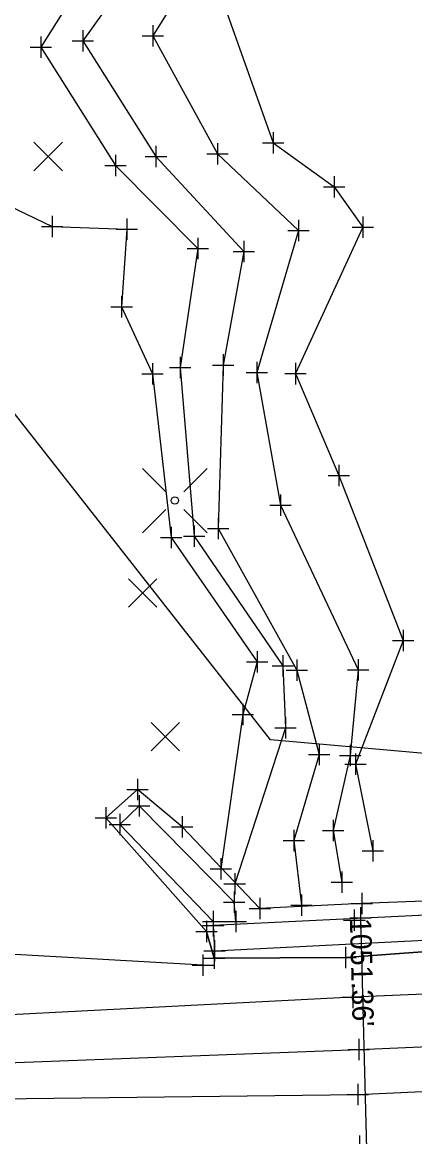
# Model space of a CAD drawing. Extents: x 211013 to 211654, y 505587 to 505872.
# Drawn here: x 211293.9 to 211312.2, y 505734.3 to 505786.5 of the extents above; entities that cross this region are included whole.
import ezdxf

# ---------------------------------------------------------------- set-up
doc = ezdxf.new("R2010")
doc.units = 0
for name, color, linetype in [('_CIVIL_CONSTRUCTION', 7, 'Continuous'), ('AP_P_PCI_Pavement', 7, 'Continuous'), ('BR_X_Rail_Centerline', 7, 'Continuous'), ('DR_X_Storm_Sewer', 7, 'Continuous'), ('DV_X_Section_VMS_Line', 7, 'Continuous'), ('GE_X_Alignment_1000_Curve_Data', 7, 'Continuous'), ('GE_X_Alignment_100_Curve_Data', 7, 'Continuous'), ('GE_X_Alignment_100_Stations', 7, 'Continuous'), ('GE_X_Alignment_500_Stations', 7, 'Continuous'), ('RW_P_Esmt_SH', 7, 'Continuous'), ('RW_X_Esmt_SH', 7, 'Continuous'), ('SC_Scratch1', 7, 'Continuous'), ('SC_Scratch10', 7, 'Continuous'), ('SC_Scratch3', 7, 'Continuous'), ('SV_X_Control_Cells_Found', 7, 'Continuous'), ('SV_X_Terrain_Break_Line', 7, 'Continuous')]:
    doc.layers.add(name, color=color, linetype=linetype)

msp = doc.modelspace()

# ---------------------------------------------------------------- linework, layer by layer
at = {"layer": '_CIVIL_CONSTRUCTION'}
msp.add_lwpolyline([(211321.115, 505749.559), (211319.635, 505750.939), (211314.771, 505745.411), (211309.764, 505745.231), (211304.987, 505744.992), (211301.351, 505748.814), (211299.272, 505750.564), (211297.783, 505749.234), (211302.497, 505743.915), (211302.86, 505742.67), (211309.002, 505742.706), (211316.82, 505743.273), (211317, 505744.987), (211318.809, 505747.038)], close=True, dxfattribs=at)
at = {"layer": 'AP_P_PCI_Pavement'}
msp.add_lwpolyline([(211327.503, 505810.82), (211323.319, 505809.929), (211317.381, 505803.934), (211308.061, 505794.296), (211303.39, 505787.114), (211305.619, 505780.843), (211308.475, 505778.776), (211309.82, 505776.891), (211306.66, 505770.032), (211308.698, 505765.258), (211311.708, 505757.543), (211309.473, 505751.753), (211310.28, 505747.694)], dxfattribs=at)
at = {"layer": 'BR_X_Rail_Centerline'}
for p, q in [((211305.491, 505752.893), (211283.423, 505780.994)), ((211344.613, 505749.38), (211305.491, 505752.893))]:
    msp.add_line(p, q, dxfattribs=at)
at = {"layer": 'DR_X_Storm_Sewer'}
msp.add_line((211309.709, 505744.552), (211310.772, 505703.905), dxfattribs=at)
at = {"layer": 'DV_X_Section_VMS_Line'}
for p, q in [((211296.713, 505786.108), (211296.713, 505785.108)), ((211299.982, 505786.35), (211299.982, 505785.35)), ((211294.742, 505785.823), (211294.742, 505784.823)), ((211296.213, 505785.608), (211297.213, 505785.608)), ((211296.713, 505785.608), (211296.713, 505785.608)), ((211299.482, 505785.85), (211300.482, 505785.85)), ((211299.982, 505785.85), (211299.982, 505785.85)), ((211294.242, 505785.323), (211295.242, 505785.323)), ((211294.742, 505785.323), (211294.742, 505785.323)), ((211305.619, 505781.343), (211305.619, 505780.343)), ((211303.013, 505780.82), (211303.013, 505779.82)), ((211305.119, 505780.843), (211306.119, 505780.843)), ((211305.619, 505780.843), (211305.619, 505780.843)), ((211298.229, 505780.271), (211298.229, 505779.271)), ((211300.132, 505780.705), (211300.132, 505779.705)), ((211302.513, 505780.32), (211303.513, 505780.32)), ((211303.013, 505780.32), (211303.013, 505780.32)), ((211297.729, 505779.771), (211298.729, 505779.771)), ((211298.229, 505779.771), (211298.229, 505779.771)), ((211299.632, 505780.205), (211300.632, 505780.205)), ((211300.132, 505780.205), (211300.132, 505780.205)), ((211308.475, 505779.276), (211308.475, 505778.276)), ((211307.975, 505778.776), (211308.975, 505778.776)), ((211308.475, 505778.776), (211308.475, 505778.776)), ((211295.266, 505777.416), (211295.266, 505776.416)), ((211298.771, 505777.292), (211298.771, 505776.292)), ((211306.808, 505777.237), (211306.808, 505776.237)), ((211309.82, 505777.391), (211309.82, 505776.391)), ((211294.766, 505776.916), (211295.766, 505776.916)), ((211295.266, 505776.916), (211295.266, 505776.916)), ((211298.271, 505776.792), (211299.271, 505776.792)), ((211298.771, 505776.792), (211298.771, 505776.792)), ((211306.308, 505776.737), (211307.308, 505776.737)), ((211306.808, 505776.737), (211306.808, 505776.737)), ((211309.32, 505776.891), (211310.32, 505776.891)), ((211309.82, 505776.891), (211309.82, 505776.891)), ((211302.084, 505776.392), (211302.084, 505775.392)), ((211304.247, 505776.25), (211304.247, 505775.25)), ((211301.584, 505775.892), (211302.584, 505775.892)), ((211302.084, 505775.892), (211302.084, 505775.892)), ((211303.747, 505775.75), (211304.747, 505775.75)), ((211304.247, 505775.75), (211304.247, 505775.75)), ((211298.524, 505773.661), (211298.524, 505772.661)), ((211298.024, 505773.161), (211299.024, 505773.161)), ((211298.524, 505773.161), (211298.524, 505773.161)), ((211303.284, 505770.937), (211303.284, 505769.937)), ((211299.968, 505770.522), (211299.968, 505769.522)), ((211301.268, 505770.827), (211301.268, 505769.827)), ((211302.784, 505770.437), (211303.784, 505770.437)), ((211303.284, 505770.437), (211303.284, 505770.437)), ((211304.847, 505770.58), (211304.847, 505769.58)), ((211306.66, 505770.532), (211306.66, 505769.532)), ((211299.468, 505770.022), (211300.468, 505770.022)), ((211299.968, 505770.022), (211299.968, 505770.022)), ((211300.768, 505770.327), (211301.768, 505770.327)), ((211301.268, 505770.327), (211301.268, 505770.327)), ((211304.347, 505770.08), (211305.347, 505770.08)), ((211304.847, 505770.08), (211304.847, 505770.08)), ((211306.16, 505770.032), (211307.16, 505770.032)), ((211306.66, 505770.032), (211306.66, 505770.032)), ((211308.698, 505765.758), (211308.698, 505764.758)), ((211308.198, 505765.258), (211309.198, 505765.258)), ((211308.698, 505765.258), (211308.698, 505765.258)), ((211305.963, 505764.381), (211305.963, 505763.381)), ((211305.463, 505763.881), (211306.463, 505763.881)), ((211305.963, 505763.881), (211305.963, 505763.881)), ((211303.046, 505763.284), (211303.046, 505762.284)), ((211300.847, 505762.861), (211300.847, 505761.861)), ((211301.924, 505762.93), (211301.924, 505761.93)), ((211302.546, 505762.784), (211303.546, 505762.784)), ((211303.046, 505762.784), (211303.046, 505762.784)), ((211300.347, 505762.361), (211301.347, 505762.361)), ((211300.847, 505762.361), (211300.847, 505762.361)), ((211301.424, 505762.43), (211302.424, 505762.43)), ((211301.924, 505762.43), (211301.924, 505762.43)), ((211311.708, 505758.043), (211311.708, 505757.043)), ((211311.208, 505757.543), (211312.208, 505757.543)), ((211311.708, 505757.543), (211311.708, 505757.543)), ((211304.863, 505757.046), (211304.863, 505756.046)), ((211306.066, 505756.847), (211306.066, 505755.847)), ((211304.363, 505756.546), (211305.363, 505756.546)), ((211304.863, 505756.546), (211304.863, 505756.546)), ((211305.566, 505756.347), (211306.566, 505756.347)), ((211306.066, 505756.347), (211306.066, 505756.347)), ((211306.73, 505756.65), (211306.73, 505755.65)), ((211309.606, 505756.673), (211309.606, 505755.673)), ((211306.23, 505756.15), (211307.23, 505756.15)), ((211306.73, 505756.15), (211306.73, 505756.15)), ((211309.106, 505756.173), (211310.106, 505756.173)), ((211309.606, 505756.173), (211309.606, 505756.173)), ((211304.191, 505754.57), (211304.191, 505753.57)), ((211303.691, 505754.07), (211304.691, 505754.07)), ((211304.191, 505754.07), (211304.191, 505754.07)), ((211306.192, 505753.949), (211306.192, 505752.949)), ((211305.692, 505753.449), (211306.692, 505753.449)), ((211306.192, 505753.449), (211306.192, 505753.449)), ((211307.777, 505752.7), (211307.777, 505751.7)), ((211309.228, 505752.656), (211309.228, 505751.656)), ((211307.277, 505752.2), (211308.277, 505752.2)), ((211307.777, 505752.2), (211307.777, 505752.2)), ((211308.728, 505752.156), (211309.728, 505752.156)), ((211309.228, 505752.156), (211309.228, 505752.156)), ((211309.473, 505752.253), (211309.473, 505751.253)), ((211308.973, 505751.753), (211309.973, 505751.753)), ((211309.473, 505751.753), (211309.473, 505751.753)), ((211299.272, 505751.064), (211299.272, 505750.064)), ((211298.772, 505750.564), (211299.772, 505750.564)), ((211299.272, 505750.564), (211299.272, 505750.564)), ((211299.339, 505750.302), (211299.339, 505749.302)), ((211297.783, 505749.734), (211297.783, 505748.734)), ((211298.839, 505749.802), (211299.839, 505749.802)), ((211299.339, 505749.802), (211299.339, 505749.802)), ((211297.283, 505749.234), (211298.283, 505749.234)), ((211297.783, 505749.234), (211297.783, 505749.234)), ((211298.443, 505749.431), (211298.443, 505748.431)), ((211301.351, 505749.314), (211301.351, 505748.314)), ((211308.422, 505749.142), (211308.422, 505748.142)), ((211297.943, 505748.931), (211298.943, 505748.931)), ((211298.443, 505748.931), (211298.443, 505748.931)), ((211300.851, 505748.814), (211301.851, 505748.814)), ((211301.351, 505748.814), (211301.351, 505748.814)), ((211306.587, 505748.682), (211306.587, 505747.682)), ((211307.922, 505748.642), (211308.922, 505748.642)), ((211308.422, 505748.642), (211308.422, 505748.642)), ((211306.087, 505748.182), (211307.087, 505748.182)), ((211306.587, 505748.182), (211306.587, 505748.182)), ((211310.28, 505748.194), (211310.28, 505747.194)), ((211309.78, 505747.694), (211310.78, 505747.694)), ((211310.28, 505747.694), (211310.28, 505747.694)), ((211303.17, 505747.354), (211303.17, 505746.354)), ((211302.67, 505746.854), (211303.67, 505746.854)), ((211303.17, 505746.854), (211303.17, 505746.854)), ((211303.816, 505746.645), (211303.816, 505745.645)), ((211308.829, 505746.725), (211308.829, 505745.725)), ((211303.316, 505746.145), (211304.316, 505746.145)), ((211303.816, 505746.145), (211303.816, 505746.145)), ((211308.329, 505746.225), (211309.329, 505746.225)), ((211308.829, 505746.225), (211308.829, 505746.225)), ((211303.798, 505745.796), (211303.798, 505744.796)), ((211304.987, 505745.492), (211304.987, 505744.492)), ((211306.944, 505745.647), (211306.944, 505744.647)), ((211309.764, 505745.731), (211309.764, 505744.731)), ((211302.816, 505744.889), (211302.816, 505743.889)), ((211303.298, 505745.296), (211304.298, 505745.296)), ((211303.798, 505745.296), (211303.798, 505745.296)), ((211303.864, 505744.88), (211303.864, 505743.88)), ((211304.487, 505744.992), (211305.487, 505744.992)), ((211304.987, 505744.992), (211304.987, 505744.992)), ((211306.444, 505745.147), (211307.444, 505745.147)), ((211306.944, 505745.147), (211306.944, 505745.147)), ((211309.264, 505745.231), (211310.264, 505745.231)), ((211309.419, 505744.947), (211309.419, 505743.947)), ((211309.764, 505745.231), (211309.764, 505745.231)), ((211302.316, 505744.389), (211303.316, 505744.389)), ((211302.497, 505744.415), (211302.497, 505743.415)), ((211302.81, 505744.69), (211302.81, 505743.69)), ((211302.816, 505744.389), (211302.816, 505744.389)), ((211303.364, 505744.38), (211304.364, 505744.38)), ((211303.864, 505744.38), (211303.864, 505744.38)), ((211308.919, 505744.447), (211309.919, 505744.447)), ((211309.419, 505744.447), (211309.419, 505744.447)), ((211301.997, 505743.915), (211302.997, 505743.915)), ((211302.31, 505744.19), (211303.31, 505744.19)), ((211302.497, 505743.915), (211302.497, 505743.915)), ((211302.81, 505744.19), (211302.81, 505744.19)), ((211302.87, 505743.515), (211302.87, 505742.515)), ((211302.318, 505742.837), (211302.318, 505741.837)), ((211302.37, 505743.015), (211303.37, 505743.015)), ((211302.86, 505743.17), (211302.86, 505742.17)), ((211302.87, 505743.015), (211302.87, 505743.015)), ((211309.002, 505743.206), (211309.002, 505742.206)), ((211301.818, 505742.337), (211302.818, 505742.337)), ((211302.318, 505742.337), (211302.318, 505742.337)), ((211302.36, 505742.67), (211303.36, 505742.67)), ((211302.86, 505742.67), (211302.86, 505742.67)), ((211308.502, 505742.706), (211309.502, 505742.706)), ((211309.002, 505742.706), (211309.002, 505742.706)), ((211309.356, 505741.335), (211309.356, 505740.335)), ((211308.856, 505740.835), (211309.856, 505740.835)), ((211309.356, 505740.835), (211309.356, 505740.835)), ((211309.635, 505738.895), (211309.635, 505737.895)), ((211309.135, 505738.395), (211310.135, 505738.395)), ((211309.635, 505738.395), (211309.635, 505738.395)), ((211309.586, 505736.786), (211309.586, 505735.786)), ((211309.086, 505736.286), (211310.086, 505736.286)), ((211309.586, 505736.286), (211309.586, 505736.286)), ((211309.664, 505734.365), (211309.664, 505733.365)), ((211309.664, 505734.365), (211309.664, 505733.365))]:
    msp.add_line(p, q, dxfattribs=at)
at = {"layer": 'GE_X_Alignment_1000_Curve_Data'}
msp.add_lwpolyline([(211356.76, 505857.013), (211347.897, 505835.841), (211344.58, 505824.107), (211344.082, 505818.007), (211333.421, 505816.177), (211323.913, 505812.659), (211316.504, 505807.568), (211303.378, 505794.919), (211296.713, 505785.608), (211300.132, 505780.205), (211304.247, 505775.75), (211303.284, 505770.437), (211303.046, 505762.784), (211306.73, 505756.15), (211307.777, 505752.2), (211306.587, 505748.182), (211306.944, 505745.147)], dxfattribs=at)
at = {"layer": 'GE_X_Alignment_100_Curve_Data'}
msp.add_lwpolyline([(211264.741, 505737.499), (211284.908, 505737.456), (211309.635, 505738.395), (211334.721, 505739.468), (211359.035, 505740.326), (211410.048, 505742.397), (211459.85, 505743.658), (211510.023, 505745.433), (211559.895, 505747.411), (211609.683, 505748.573), (211648.059, 505750.315)], dxfattribs=at)
at = {"layer": 'GE_X_Alignment_100_Stations'}
for points in [[(211333.611, 505861.656), (211320.184, 505846.845), (211302.496, 505826.303), (211296.037, 505815.121), (211294.576, 505796.638), (211295.648, 505794.362), (211291.368, 505793.326), (211288.466, 505788.138), (211290.773, 505779.079), (211295.266, 505776.916), (211298.771, 505776.792), (211298.524, 505773.161), (211299.968, 505770.022), (211300.847, 505762.361), (211304.863, 505756.546), (211304.191, 505754.07), (211303.17, 505746.854)], [(211302.318, 505742.337), (211290.21, 505743.029), (211275.686, 505746.007)]]:
    msp.add_lwpolyline(points, dxfattribs=at)
at = {"layer": 'GE_X_Alignment_500_Stations'}
msp.add_lwpolyline([(211014.958, 505726.701), (211059.158, 505728.206), (211109.787, 505730.119), (211159.491, 505731.893), (211208.807, 505733.151), (211259.883, 505734.994), (211284.984, 505735.986), (211309.586, 505736.286), (211335.024, 505737.47), (211359.187, 505738.245), (211410.256, 505740.038), (211459.776, 505741.71), (211509.557, 505743.255), (211560.066, 505744.756), (211609.925, 505746.61), (211648.161, 505748.077)], dxfattribs=at)
at = {"layer": 'RW_P_Esmt_SH'}
for points in [[(211351.822, 505854.454), (211346.493, 505836.563), (211343.46, 505825.328), (211342.052, 505819.968), (211331.933, 505819.083), (211323.28, 505814.802), (211316.095, 505808.714), (211301.705, 505796.376), (211294.742, 505785.323), (211298.229, 505779.771), (211302.084, 505775.892), (211301.268, 505770.327), (211301.924, 505762.43), (211306.066, 505756.347), (211306.192, 505753.449), (211303.816, 505746.145)], [(211358.553, 505853.678), (211348.819, 505834.008), (211346.411, 505822.415), (211345.492, 505817.268), (211335.334, 505814.753), (211325.939, 505811.11), (211322.478, 505810.52), (211318.221, 505806.357), (211305.276, 505794.35), (211299.982, 505785.85), (211303.013, 505780.32), (211306.808, 505776.737), (211304.847, 505770.08), (211305.963, 505763.881), (211309.606, 505756.173), (211309.228, 505752.156), (211308.422, 505748.642), (211308.829, 505746.225)]]:
    msp.add_lwpolyline(points, dxfattribs=at)
at = {"layer": 'RW_X_Esmt_SH'}
for p, q in [((211294.416, 505779.532), (211295.75, 505780.867)), ((211294.416, 505780.867), (211295.75, 505779.532)), ((211298.842, 505759.097), (211300.176, 505760.432)), ((211298.842, 505760.432), (211300.176, 505759.097)), ((211299.906, 505752.367), (211301.24, 505753.702)), ((211299.906, 505753.702), (211301.24, 505752.367))]:
    msp.add_line(p, q, dxfattribs=at)
at = {"layer": 'SC_Scratch1'}
for p, q in [((211309.709, 505745.052), (211309.709, 505744.052)), ((211309.209, 505744.552), (211310.209, 505744.552)), ((211309.709, 505744.552), (211309.709, 505744.552))]:
    msp.add_line(p, q, dxfattribs=at)
at = {"layer": 'SC_Scratch10'}
for points in [[(211299.339, 505749.802), (211298.443, 505748.931), (211302.816, 505744.389), (211303.864, 505744.38), (211303.798, 505745.296)], [(211302.81, 505744.19), (211302.87, 505743.015), (211316.685, 505743.715), (211316.627, 505744.873)]]:
    msp.add_lwpolyline(points, close=True, dxfattribs=at)
at = {"layer": 'SC_Scratch3'}
for p, q in [((211299.506, 505765.599), (211300.6, 505764.506)), ((211301.433, 505764.506), (211302.525, 505765.599)), ((211299.506, 505762.581), (211300.6, 505763.674)), ((211301.433, 505763.674), (211302.525, 505762.581))]:
    msp.add_line(p, q, dxfattribs=at)
msp.add_circle((211301.016, 505764.096), 0.17, dxfattribs=at)
at = {"layer": 'SV_X_Control_Cells_Found'}
for p, q in [((211334.72, 505741.919), (211309.356, 505740.835)), ((211309.356, 505740.835), (211285.607, 505739.628))]:
    msp.add_line(p, q, dxfattribs=at)
at = {"layer": 'SV_X_Terrain_Break_Line'}
msp.add_lwpolyline([(211321.115, 505749.559), (211317, 505744.987), (211316.82, 505743.273), (211309.002, 505742.706), (211302.86, 505742.67), (211302.497, 505743.915), (211297.783, 505749.234)], dxfattribs=at)

# ---------------------------------------------------------------- texts
at = {"layer": 'SC_Scratch1'}
msp.add_text("1051.36'", height=1, rotation=271.4981, dxfattribs=at).set_placement((211309.209, 505744.539))

doc.saveas('drawing.dxf')
